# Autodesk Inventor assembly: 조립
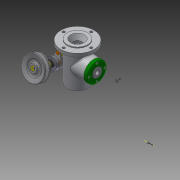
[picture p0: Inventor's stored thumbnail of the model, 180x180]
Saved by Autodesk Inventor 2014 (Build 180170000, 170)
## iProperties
Created: 2016-08
Part Number: 조립
Document SubType Name: Assembly
Designer: owner
Author: owner
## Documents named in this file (25)
- C:\Users\owner\Desktop\조립.iam
- C:\Users\owner\Desktop\본체.ipt
- C:\Users\owner\Desktop\460807V1005\V-벨트풀리.ipt
- C:\Users\owner\Desktop\460807V1005\너트 M10.ipt
- C:\Users\owner\Desktop\460807V1005\링크.ipt
- C:\Users\owner\Desktop\460807V1005\멈춤링 15 x 1.ipt
- C:\Users\owner\Desktop\460807V1005\멈춤링 35x1.6.ipt
- C:\Users\owner\Desktop\460807V1005\베어링 15 x 35 x 11.ipt
- C:\Users\owner\Desktop\460807V1005\볼트 M4 x 10.ipt
- C:\Users\owner\Desktop\460807V1005\볼트 M4 x 12.ipt
- C:\Users\owner\Desktop\460807V1005\부시1.ipt
- C:\Users\owner\Desktop\460807V1005\부시2.ipt
- C:\Users\owner\Desktop\460807V1005\분할핀 1.6 x 12.ipt
- C:\Users\owner\Desktop\460807V1005\사이드 커버.ipt
- 사이드 커버.ipt
- C:\Users\owner\Desktop\460807V1005\슬라이더.ipt
- C:\Users\owner\Desktop\460807V1005\오일 실 15 25 7.ipt
- C:\Users\owner\Desktop\460807V1005\와셔 4x16.ipt
- C:\Users\owner\Desktop\460807V1005\와셔 10x21.ipt
- C:\Users\owner\Desktop\460807V1005\클래스터 핀 6 x 24.ipt
- C:\Users\owner\Desktop\460807V1005\키 4 x 4 x 18.ipt
- C:\Users\owner\Desktop\460807V1005\탑 부시.ipt
- C:\Users\owner\Desktop\460807V1005\탑 커버.ipt
- 탑 커버.ipt
- C:\Users\owner\Desktop\460807V1005\편심축.ipt
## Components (6 placed, 3 different names)
1. V-벨트풀리:1 — 각도:2
2. ISO 4017 M4 x 10:1
3. ISO 4762 M4 x 12:1
4. ISO 4762 M4 x 12:2
5. ISO 4762 M4 x 12:3
6. ISO 4762 M4 x 12:4
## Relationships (1: Angle 1)
- 각도:2 [Angle]: V-벨트풀리:1
